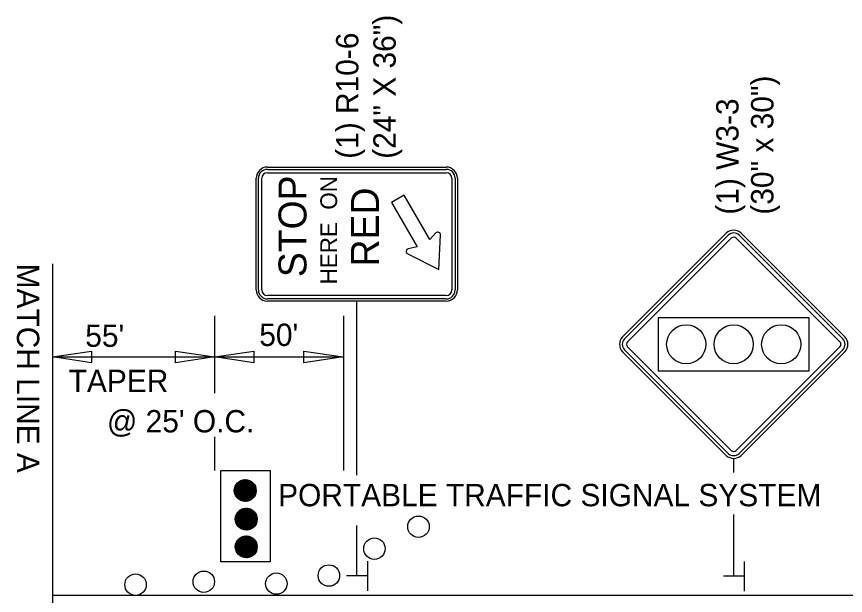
# Model space of a CAD drawing. Extents: x 1927831 to 1930787, y 596452 to 597699.
# Drawn here: x 1927831.5 to 1928053.9, y 597037.3 to 597192.8 of the extents above; entities that cross this region are included whole.
import ezdxf

# ---------------------------------------------------------------- set-up
doc = ezdxf.new("R2010")
doc.units = 0
for name, color, linetype in [('Default', 7, 'Continuous'), ('P_TC_Signs_Permanent', 7, 'Continuous'), ('R_Annotation', 7, 'Continuous')]:
    doc.layers.add(name, color=color, linetype=linetype)

msp = doc.modelspace()

# ---------------------------------------------------------------- linework, layer by layer
at = {"layer": 'Default'}
for p, q in [((1927841.07, 597126.4), (1927841.07, 597001.76)), ((1927884.63, 597112.39), (1927884.63, 597091.6)), ((1927919.2, 597112.39), (1927919.2, 597070.81)), ((1927841.07, 597101.35), (1927851.62, 597102.93)), ((1927851.62, 597102.93), (1927851.62, 597099.77)), ((1927874.09, 597099.77), (1927874.09, 597102.93)), ((1927874.09, 597102.93), (1927884.63, 597101.35)), ((1927884.63, 597101.35), (1927895.17, 597102.93)), ((1927895.17, 597102.93), (1927895.17, 597099.77)), ((1927908.54, 597099.77), (1927908.54, 597102.93)), ((1927908.54, 597102.93), (1927919.08, 597101.35)), ((1927851.62, 597099.77), (1927841.07, 597101.35)), ((1927841.07, 597101.35), (1927884.63, 597101.35)), ((1927884.63, 597101.35), (1927874.09, 597099.77)), ((1927884.63, 597101.35), (1927919.08, 597101.35)), ((1927895.17, 597099.77), (1927884.63, 597101.35)), ((1927919.08, 597101.35), (1927908.54, 597099.77)), ((1927884.63, 597079.86), (1927884.63, 597070.81)), ((1927889.9, 597065.5), (1927892.8, 597068.4)), ((1927889.91, 597065.32), (1927892.98, 597068.39)), ((1927889.91, 597065.69), (1927892.61, 597068.39)), ((1927889.92, 597065.15), (1927893.15, 597068.38)), ((1927889.94, 597064.99), (1927893.31, 597068.36)), ((1927889.94, 597065.89), (1927892.41, 597068.36)), ((1927889.97, 597064.84), (1927893.46, 597068.33)), ((1927889.98, 597066.12), (1927892.19, 597068.32)), ((1927890, 597064.69), (1927893.61, 597068.3)), ((1927890.04, 597064.55), (1927893.75, 597068.26)), ((1927890.05, 597066.37), (1927891.93, 597068.25)), ((1927890.09, 597064.42), (1927893.88, 597068.21)), ((1927890.14, 597064.29), (1927894.01, 597068.16)), ((1927890.16, 597066.66), (1927891.64, 597068.14)), ((1927890.2, 597064.17), (1927894.13, 597068.1)), ((1927890.26, 597064.05), (1927894.25, 597068.04)), ((1927890.33, 597063.93), (1927894.37, 597067.97)), ((1927890.38, 597067.06), (1927891.24, 597067.92)), ((1927890.4, 597063.82), (1927894.48, 597067.9)), ((1927890.47, 597063.72), (1927894.58, 597067.83)), ((1927890.55, 597063.61), (1927894.69, 597067.75)), ((1927890.63, 597063.52), (1927894.79, 597067.67)), ((1927890.72, 597063.42), (1927894.88, 597067.58)), ((1927890.81, 597063.33), (1927894.97, 597067.49)), ((1927890.91, 597063.24), (1927895.06, 597067.4)), ((1927891, 597063.16), (1927895.14, 597067.3)), ((1927891.11, 597063.08), (1927895.22, 597067.19)), ((1927891.21, 597063.01), (1927895.29, 597067.09)), ((1927891.32, 597062.94), (1927895.36, 597066.98)), ((1927891.44, 597062.87), (1927895.43, 597066.86)), ((1927891.56, 597062.81), (1927895.49, 597066.74)), ((1927891.68, 597062.75), (1927895.55, 597066.62)), ((1927891.81, 597062.7), (1927895.6, 597066.49)), ((1927891.94, 597062.66), (1927895.65, 597066.36)), ((1927892.08, 597062.61), (1927895.69, 597066.22)), ((1927892.23, 597062.58), (1927895.72, 597066.07)), ((1927892.38, 597062.55), (1927895.75, 597065.92)), ((1927892.54, 597062.53), (1927895.77, 597065.76)), ((1927892.71, 597062.52), (1927895.78, 597065.59)), ((1927892.89, 597062.51), (1927895.79, 597065.41)), ((1927893.08, 597062.52), (1927895.78, 597065.22)), ((1927893.28, 597062.55), (1927895.75, 597065.02)), ((1927893.51, 597062.59), (1927895.71, 597064.79)), ((1927893.76, 597062.66), (1927895.64, 597064.54)), ((1927894.05, 597062.77), (1927895.53, 597064.25)), ((1927894.45, 597062.99), (1927895.31, 597063.85)), ((1927890.17, 597057.84), (1927893.07, 597060.74)), ((1927890.18, 597057.66), (1927893.25, 597060.74)), ((1927890.18, 597058.03), (1927892.88, 597060.73)), ((1927890.19, 597057.49), (1927893.42, 597060.72)), ((1927890.21, 597058.23), (1927892.68, 597060.71)), ((1927890.21, 597057.33), (1927893.58, 597060.7)), ((1927890.24, 597057.18), (1927893.73, 597060.67)), ((1927890.25, 597058.46), (1927892.45, 597060.66)), ((1927890.27, 597057.03), (1927893.88, 597060.64)), ((1927890.31, 597056.9), (1927894.02, 597060.6)), ((1927890.32, 597058.71), (1927892.2, 597060.59)), ((1927890.36, 597056.76), (1927894.15, 597060.55)), ((1927890.41, 597056.63), (1927894.28, 597060.5)), ((1927890.43, 597059), (1927891.91, 597060.48)), ((1927890.47, 597056.51), (1927894.4, 597060.44)), ((1927890.53, 597056.39), (1927894.52, 597060.38)), ((1927890.6, 597056.27), (1927894.64, 597060.31)), ((1927890.65, 597059.4), (1927891.51, 597060.26)), ((1927890.67, 597056.16), (1927894.75, 597060.24)), ((1927890.74, 597056.06), (1927894.85, 597060.17)), ((1927890.82, 597055.95), (1927894.96, 597060.09)), ((1927890.9, 597055.86), (1927895.05, 597060.01)), ((1927890.99, 597055.76), (1927895.15, 597059.92)), ((1927891.08, 597055.67), (1927895.24, 597059.83)), ((1927891.17, 597055.58), (1927895.33, 597059.74)), ((1927891.27, 597055.5), (1927895.41, 597059.64)), ((1927891.38, 597055.42), (1927895.49, 597059.54)), ((1927891.48, 597055.35), (1927895.56, 597059.43)), ((1927891.59, 597055.28), (1927895.63, 597059.32)), ((1927891.71, 597055.21), (1927895.7, 597059.2)), ((1927891.83, 597055.15), (1927895.76, 597059.08)), ((1927891.95, 597055.09), (1927895.82, 597058.96)), ((1927892.08, 597055.04), (1927895.87, 597058.83)), ((1927892.21, 597055), (1927895.91, 597058.7)), ((1927892.35, 597054.96), (1927895.96, 597058.56)), ((1927892.5, 597054.92), (1927895.99, 597058.41)), ((1927892.65, 597054.89), (1927896.02, 597058.26)), ((1927892.81, 597054.87), (1927896.04, 597058.1)), ((1927892.98, 597054.86), (1927896.05, 597057.93)), ((1927893.16, 597054.86), (1927896.06, 597057.75)), ((1927893.35, 597054.86), (1927896.05, 597057.56)), ((1927893.55, 597054.89), (1927896.02, 597057.36)), ((1927893.78, 597054.93), (1927895.98, 597057.13)), ((1927894.03, 597055), (1927895.91, 597056.88)), ((1927894.32, 597055.11), (1927895.8, 597056.59)), ((1927894.72, 597055.33), (1927895.58, 597056.19)), ((1927890.17, 597050.32), (1927893.15, 597053.3)), ((1927890.18, 597050.5), (1927892.97, 597053.3)), ((1927890.18, 597050.15), (1927893.33, 597053.29)), ((1927890.19, 597050.7), (1927892.77, 597053.28)), ((1927890.2, 597049.98), (1927893.49, 597053.28)), ((1927890.22, 597049.83), (1927893.65, 597053.25)), ((1927890.23, 597050.92), (1927892.56, 597053.25)), ((1927890.25, 597049.68), (1927893.8, 597053.22)), ((1927890.28, 597051.15), (1927892.32, 597053.19)), ((1927890.29, 597049.53), (1927893.94, 597053.18)), ((1927890.33, 597049.4), (1927894.08, 597053.14)), ((1927890.37, 597051.42), (1927892.05, 597053.1)), ((1927890.38, 597049.26), (1927894.21, 597053.09)), ((1927890.44, 597049.14), (1927894.33, 597053.03)), ((1927890.5, 597049.02), (1927894.46, 597052.98)), ((1927890.53, 597051.76), (1927891.71, 597052.94)), ((1927890.56, 597048.9), (1927894.57, 597052.91)), ((1927890.63, 597048.79), (1927894.69, 597052.84)), ((1927890.7, 597048.68), (1927894.8, 597052.77)), ((1927890.78, 597048.57), (1927894.9, 597052.7)), ((1927890.86, 597048.47), (1927895, 597052.62)), ((1927890.94, 597048.37), (1927895.1, 597052.53)), ((1927891.03, 597048.28), (1927895.19, 597052.44)), ((1927891.12, 597048.19), (1927895.28, 597052.35)), ((1927891.22, 597048.11), (1927895.36, 597052.25)), ((1927891.32, 597048.03), (1927895.44, 597052.15)), ((1927891.42, 597047.95), (1927895.52, 597052.05)), ((1927891.53, 597047.88), (1927895.59, 597051.94)), ((1927891.64, 597047.81), (1927895.66, 597051.83)), ((1927891.76, 597047.75), (1927895.73, 597051.71)), ((1927891.88, 597047.69), (1927895.78, 597051.59)), ((1927892.14, 597047.58), (1927895.89, 597051.33)), ((1927892.27, 597047.54), (1927895.93, 597051.2)), ((1927892.42, 597047.5), (1927895.97, 597051.05)), ((1927892.57, 597047.47), (1927896, 597050.91)), ((1927892.72, 597047.44), (1927896.03, 597050.75)), ((1927892.89, 597047.42), (1927896.05, 597050.59)), ((1927893.06, 597047.42), (1927896.06, 597050.41)), ((1927893.24, 597047.42), (1927896.05, 597050.23)), ((1927893.44, 597047.43), (1927896.04, 597050.04)), ((1927893.65, 597047.46), (1927896.01, 597049.82)), ((1927893.88, 597047.52), (1927895.95, 597049.59)), ((1927894.15, 597047.6), (1927895.87, 597049.32)), ((1927894.48, 597047.75), (1927895.72, 597048.99)), ((1927895.05, 597048.14), (1927895.33, 597048.42)), ((1927925.62, 597046.52), (1927925.62, 597038.52)), ((1928026.77, 597046.42), (1928026.77, 597038.42)), ((1927925.51, 597042.54), (1927920.04, 597042.54)), ((1928026.65, 597042.44), (1928021.19, 597042.44)), ((1927841.07, 597037.34), (1928485.68, 597037.29))]:
    msp.add_line(p, q, dxfattribs=at)
msp.add_lwpolyline([(1927886.27, 597070.81), (1927899.56, 597070.81), (1927899.56, 597046.27), (1927886.27, 597046.27)], close=True, dxfattribs=at)
for centre, radius in [((1927892.84, 597065.46), 2.94), ((1927893.11, 597057.8), 2.94), ((1927939.33, 597055.74), 2.88), ((1927893.11, 597050.36), 2.94), ((1927927.51, 597049.86), 2.88), ((1927915.28, 597042.64), 2.88), ((1927863.4, 597040.19), 2.88), ((1927881.71, 597040.97), 2.88), ((1927901.19, 597040.47), 2.88)]:
    msp.add_circle(centre, radius, dxfattribs=at)
at = {"layer": 'P_TC_Signs_Permanent'}
for p, q in [((1927898.77, 597152.35), (1927946.77, 597152.35)), ((1927898.77, 597151.75), (1927946.77, 597151.75)), ((1927895.77, 597119.35), (1927895.77, 597149.35)), ((1927896.37, 597119.35), (1927896.37, 597149.35)), ((1927897.27, 597119.35), (1927897.27, 597149.35)), ((1927898.77, 597150.85), (1927946.77, 597150.85)), ((1927948.27, 597149.35), (1927948.27, 597119.35)), ((1927949.17, 597149.35), (1927949.17, 597119.35)), ((1927949.77, 597149.35), (1927949.77, 597119.35)), ((1927994.09, 597106.74), (1928021.93, 597134.58)), ((1927994.62, 597106.21), (1928022.46, 597134.05)), ((1928025.38, 597134.05), (1928053.22, 597106.21)), ((1928025.91, 597134.58), (1928053.75, 597106.74)), ((1928023.26, 597133.26), (1927995.41, 597105.42)), ((1928052.42, 597105.42), (1928024.58, 597133.26)), ((1927946.77, 597117.85), (1927898.77, 597117.85)), ((1927946.77, 597116.95), (1927898.77, 597116.95)), ((1927946.77, 597116.35), (1927898.77, 597116.35)), ((1928021.93, 597074.92), (1927994.09, 597102.77)), ((1928022.46, 597075.45), (1927994.62, 597103.3)), ((1927995.41, 597104.09), (1928023.26, 597076.25)), ((1928024.58, 597076.25), (1928052.42, 597104.09)), ((1928053.22, 597103.3), (1928025.38, 597075.45)), ((1928053.75, 597102.77), (1928025.91, 597074.92))]:
    msp.add_line(p, q, dxfattribs=at)
for points in [[(1927944.02, 597134.66), (1927942.38, 597132.91), (1927935.49, 597144.84), (1927932.08, 597142.87), (1927938.97, 597130.94), (1927936.6, 597130.4)], [(1927936.44, 597129.05), (1927944.76, 597124.85), (1927945.27, 597134.12)]]:
    msp.add_lwpolyline(points, dxfattribs=at)
msp.add_lwpolyline([(1928044.17, 597097.63), (1928044.17, 597111.88), (1928003.67, 597111.88), (1928003.67, 597097.63)], close=True, dxfattribs=at)
for centre in [(1928011.17, 597104.75), (1928023.92, 597104.75), (1928036.67, 597104.75)]:
    msp.add_circle(centre, 5.25, dxfattribs=at)
for centre, radius, start, end in [((1927898.77, 597149.35), 3, 90, 180), ((1927898.77, 597149.35), 2.4, 90, 180), ((1927946.77, 597149.35), 3, 360, 90), ((1927946.77, 597149.35), 2.4, 360, 90), ((1927898.77, 597149.35), 1.5, 90, 180), ((1927946.77, 597149.35), 1.5, 360, 90), ((1927944.55, 597134.16), 0.72, 356.857, 136.6377), ((1928023.92, 597132.6), 2.81, 45, 135), ((1928023.92, 597132.6), 2.06, 45, 135), ((1928023.92, 597132.6), 0.937, 45, 135), ((1927936.76, 597129.69), 0.72, 103.0349, 243.2286), ((1927898.77, 597119.35), 3, 180, 270), ((1927898.77, 597119.35), 2.4, 180, 270), ((1927898.77, 597119.35), 1.5, 180, 270), ((1927946.77, 597119.35), 3, 270, 360), ((1927946.77, 597119.35), 2.4, 270, 360), ((1927946.77, 597119.35), 1.5, 270, 360), ((1927996.08, 597104.75), 2.81, 135, 225), ((1928051.76, 597104.75), 2.81, 315, 45), ((1927996.08, 597104.75), 2.06, 135, 225), ((1927996.08, 597104.75), 0.937, 135, 225), ((1928051.76, 597104.75), 0.938, 315, 45), ((1928051.76, 597104.75), 2.06, 315, 45), ((1928023.92, 597076.91), 2.06, 225, 315), ((1928023.92, 597076.91), 0.938, 225, 315), ((1928023.92, 597076.91), 2.81, 225, 315)]:
    msp.add_arc(centre, radius, start, end, dxfattribs=at)
at = {"layer": 'R_Annotation'}
for p, q in [((1927922.77, 597069.6), (1927922.77, 597116.35)), ((1928023.92, 597070.33), (1928023.92, 597074.1)), ((1928023.92, 597042.44), (1928023.92, 597059.06)), ((1927922.77, 597042.54), (1927922.77, 597056.07))]:
    msp.add_line(p, q, dxfattribs=at)

# ---------------------------------------------------------------- texts
at = {"layer": 'Default'}
for s, rotation, p in [('MATCH LINE A', 270, (1927831.56, 597126.4)), ("  55' ", 360, (1927845.45, 597104.06)), ("50'", 360, (1927896.6, 597104.3)), ('TAPER', 360, (1927845.45, 597091.92)), (" @ 25' O.C.", 360, (1927853.5, 597081.09)), ('PORTABLE TRAFFIC SIGNAL SYSTEM', 360, (1927901.66, 597061.24))]:
    msp.add_text(s, height=6, rotation=rotation, dxfattribs=at).set_placement(p)
at = {"layer": 'P_TC_Signs_Permanent'}
for s, height, p in [('STOP', 7.5, (1927909.27, 597122.79)), ('HERE  ON', 4.5, (1927917.49, 597120.85)), ('RED', 7.5, (1927928.71, 597125.68))]:
    msp.add_text(s, height=height, rotation=90, dxfattribs=at).set_placement(p)
at = {"layer": 'R_Annotation'}
for s, height, p in [('(24" X 36")', 5.9996, (1927933.21, 597154.59)), ('(1) R10-6', 6, (1927923.2, 597154.59)), ('(30" x 30")', 5.9996, (1928034.58, 597139.58)), ('(1) W3-3', 6, (1928025.22, 597139.58))]:
    msp.add_text(s, height=height, rotation=90, dxfattribs=at).set_placement(p)

doc.saveas('drawing.dxf')
